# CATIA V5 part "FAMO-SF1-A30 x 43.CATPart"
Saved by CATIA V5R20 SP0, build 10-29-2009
Part number: FAMO-SF1-A30 x 43
Definition: NONE
Nomenclature: FAMO-SF1-A30 x 43
Source: Unknown
Description: FAMO-SF1-A30 x 43
Bounding box of the stored display mesh (mm): x -13 to 30, y -26.5 to 26.5, z -26.5 to 26.5
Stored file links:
  C:\Users\Utente\Desktop\IO LAVORO\3D X SITO CF\X SITO\FAMO\FAMO-SF1-A30 x 43.CATPart
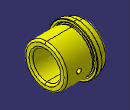
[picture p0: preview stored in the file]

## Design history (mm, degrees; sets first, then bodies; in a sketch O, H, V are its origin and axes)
Body1 "FAMO-SF1-A30 x 43" (main body)
  Solid1: solid without history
